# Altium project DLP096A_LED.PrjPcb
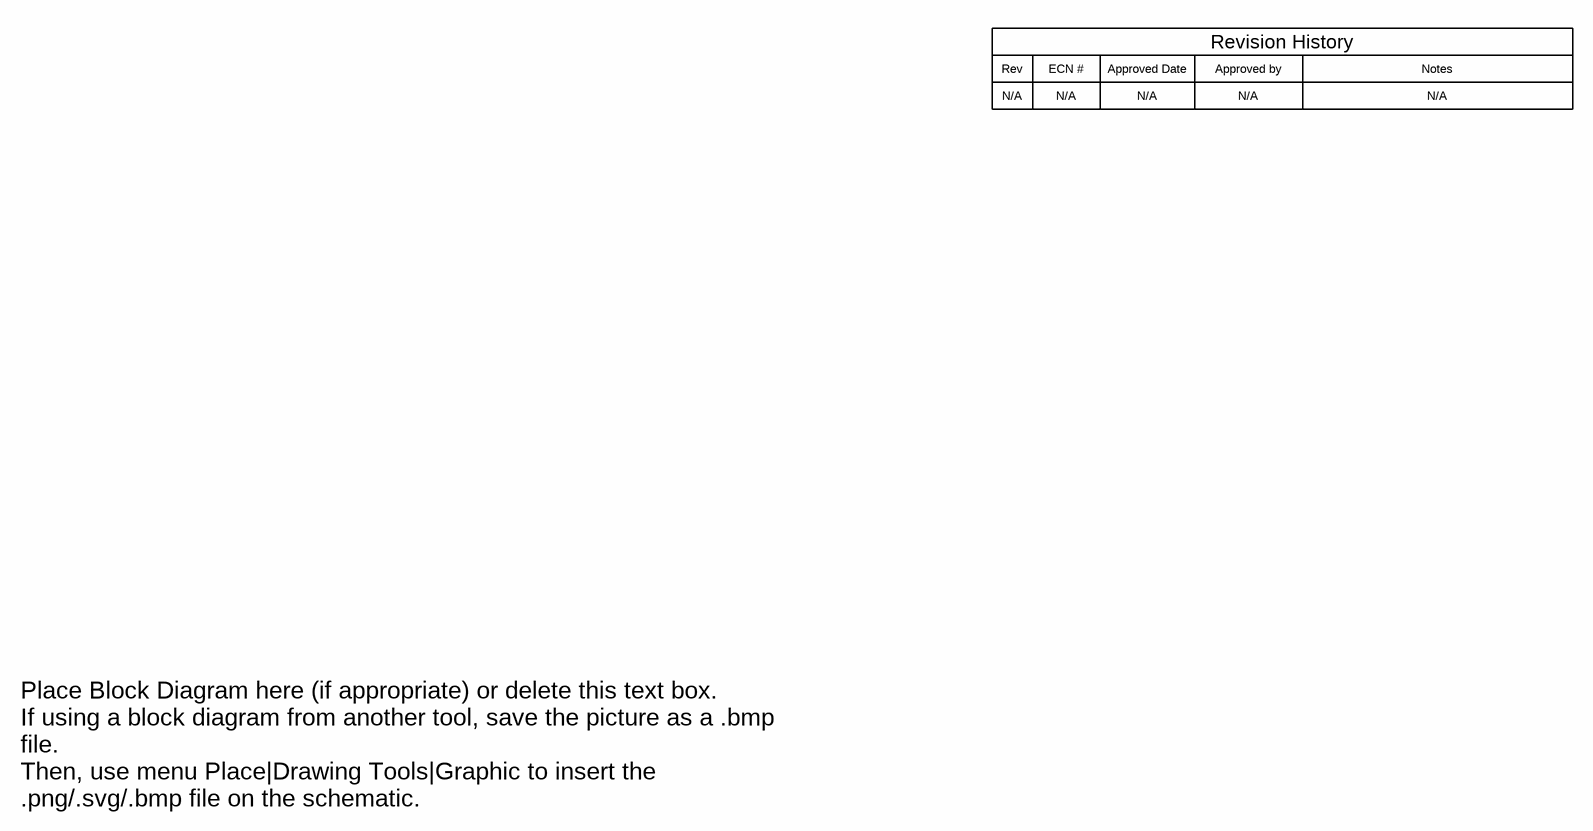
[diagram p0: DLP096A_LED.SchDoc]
CopyrightYear: 2023; PCB_Layout: A. Whitehead; PCB_Rev: A; PRJ_Customer: Public Release; PRJ_Engineer: A. Whitehead; PRJ_Number: DLP096A_LED; PRJ_Title: DLP2021AM263Q1EVM LED Adapter; SCH_Rev: A; TechSupport: http://www.ti.com/support; TID: N/A
3 sheets, 11 parts. Net scope: global (net labels, ports and power ports of the same name join across sheets).
Board file: DLP096A_LED.PcbDoc
Sheets:
  DLP096A_LED.SchDoc
  DLP096A_LED_BlankSheet.SchDoc
  DLP096A_LED_Hardware.SchDoc

## Sheet DLP096A_LED.SchDoc
size 431 x 279 mm; Date: Not shown in title block; ApprovedBy: Not shown in title block; CheckedBy: Not shown in title block; Author: Not shown in title block; CompanyName: Not shown in title block; Engineer: Not shown in title block; Organization: Not shown in title block; Address1: Not shown in title block; Address2: Not shown in title block; Address3: Not shown in title block; Address4: Not shown in title block; DocumentNumber: 1; Revision: Use project parameter SCH_Rev; SheetNumber: 1; SheetTotal: 3; PageSetup: Record=PageOptions¦CenterHorizontal=True¦CenterVertical=True¦PrintScale=1.00¦XCorrection=1.00¦YCorrection=1.00¦PrintKind=0¦BorderSize=5000000¦LeftOffset=0¦BottomOffset=0¦Orientation=2¦PaperLength=1000¦PaperWidth=1000¦Scale=100¦PaperSource=15¦PrintQuality=600¦MediaType=1¦DitherType=10¦PaperKind=Letter¦PrintScaleMode=1

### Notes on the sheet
- Rev
- N/A
- ECN #
- Approved Date
- Approved by
- Revision History
- Notes
- Place Block Diagram here (if appropriate) or delete this text box.
  If using a block diagram from another tool, save the picture as a .bmp file.
  Then, use menu Place|Drawing Tools|Graphic to insert the .png/.svg/.bmp file on the schematic.

## Sheet DLP096A_LED_BlankSheet.SchDoc
size 431 x 279 mm; Date: Not shown in title block; ApprovedBy: Not shown in title block; CheckedBy: Not shown in title block; Author: Not shown in title block; CompanyName: Not shown in title block; Engineer: Not shown in title block; Organization: Not shown in title block; Address1: Not shown in title block; Address2: Not shown in title block; Address3: Not shown in title block; Address4: Not shown in title block; DocumentNumber: 2; Revision: Use project parameter SCH_Rev; SheetNumber: 2; SheetTotal: 3; PageSetup: Record=PageOptions¦CenterHorizontal=True¦CenterVertical=True¦PrintScale=1.00¦XCorrection=1.00¦YCorrection=1.00¦PrintKind=0¦BorderSize=5000000¦LeftOffset=0¦BottomOffset=0¦Orientation=2¦PaperLength=1000¦PaperWidth=1000¦Scale=100¦PaperSource=15¦PrintQuality=600¦MediaType=1¦DitherType=10¦PaperKind=Letter¦PrintScaleMode=1
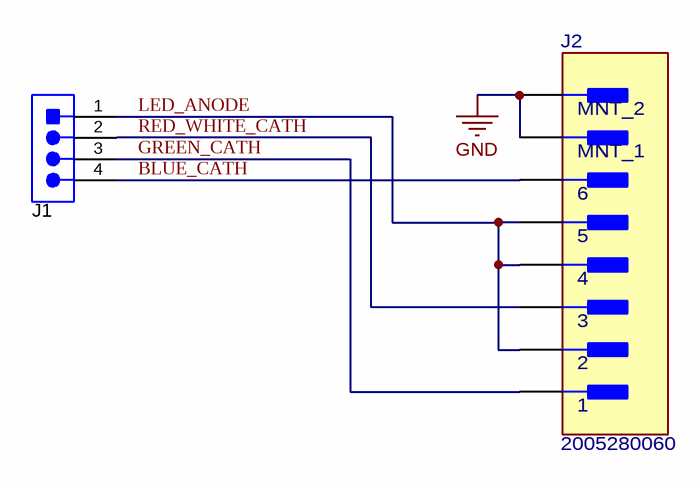
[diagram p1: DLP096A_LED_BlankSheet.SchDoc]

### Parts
J1  TSW-104-07-G-S  [TSW-104-07-G-S]  (value not drawn)
J2  2005280060  [FP-2005280060_CONN_11MM2_5MM25-MFG]

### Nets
GND: J2.7(MNT_1) J2.8(MNT_2)
BLUE_CATH: J1.4 J2.6
GREEN_CATH: J1.3 J2.1
LED_ANODE: J1.1 J2.2 J2.4 J2.5
RED_WHITE_CATH: J1.2 J2.3

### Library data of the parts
J1 = CMP-0075409-2: Header, 100mil, 4x1, Gold, TH; Manufacturer: Samtec; Pitch_mm: 2.54; Cert_VDE: N; Gender: Male; Cert_CSA: Y; Voltage_V: 550V; Green_REACh: Passed; Current_A: 6.3A; Green_Lifecycle: Active; Row_Count: 1
J2 = CMP-0090189-1: 6 Position FFC, FPC Connector Contacts, Bottom 0.039" (1.00mm) Surface Mount, Right Angle from Molex; Conn Gender: Male; Is Female: yes; DUT-Pitch_mm: 1mm; ContactFinish: Gold,Nickel; SizeZ_mm: 4.15mm; Voltage_V: 125V; AEC Qualified: No; Current_A: 1A

## Sheet DLP096A_LED_Hardware.SchDoc
size 431 x 279 mm; Date: Not shown in title block; ApprovedBy: Not shown in title block; CheckedBy: Not shown in title block; Author: Not shown in title block; CompanyName: Not shown in title block; Engineer: Not shown in title block; Organization: Not shown in title block; Address1: Not shown in title block; Address2: Not shown in title block; Address3: Not shown in title block; Address4: Not shown in title block; DocumentNumber: 3; Revision: Use project parameter SCH_Rev; SheetNumber: 3; SheetTotal: 3; PageSetup: Record=PageOptions¦CenterHorizontal=True¦CenterVertical=True¦PrintScale=1.00¦XCorrection=1.00¦YCorrection=1.00¦PrintKind=0¦BorderSize=5000000¦LeftOffset=0¦BottomOffset=0¦Orientation=2¦PaperLength=1000¦PaperWidth=1000¦Scale=100¦PaperSource=15¦PrintQuality=600¦MediaType=1¦DitherType=10¦PaperKind=Letter¦PrintScaleMode=1
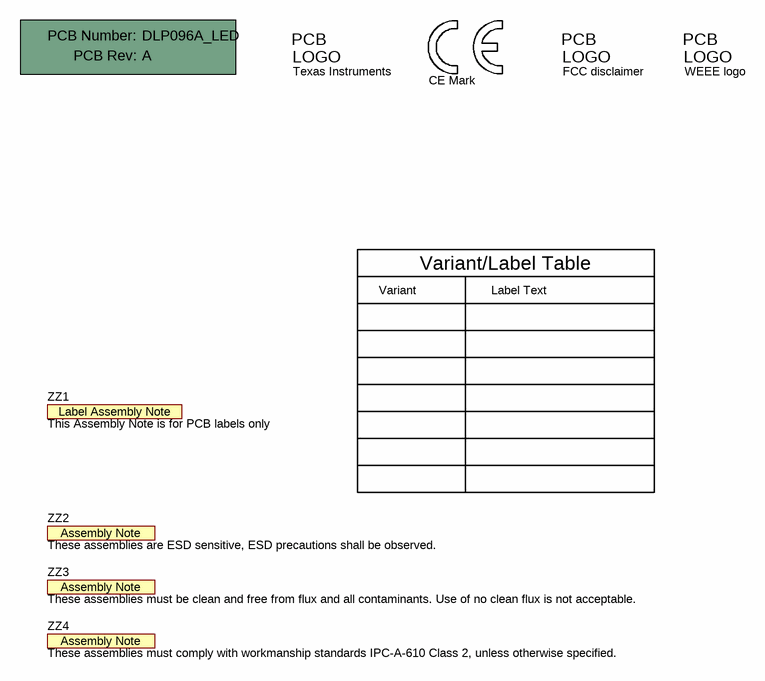
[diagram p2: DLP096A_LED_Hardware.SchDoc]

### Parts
!PCB  Printed Circuit Board  (value not drawn)  (mechanical)
Logo1  Texas Instruments  [TI_Symbol_Overlay_Small]  (no BOM)
Logo2  CE Mark  [CE_Mark_5mm]  (no BOM)
Logo3  FCC disclaimer  [FCC_disclaimer]  (no BOM)
Logo4  WEEE logo  [WEEE_Minimum]  (no BOM)
ZZ1  This Assembly Note is for PCB labels only  [AssemblyNoteLabel]  (no BOM)
ZZ2  These assemblies are ESD sensitive, ESD precautions shall be observed.  [AssemblyNote]  (no BOM)
ZZ3  These assemblies must be clean and free from flux and all contaminants. Use of no clean flux is not acceptable.  [AssemblyNote]  (no BOM)
ZZ4  These assemblies must comply with workmanship standards IPC-A-610 Class 2, unless otherwise specified.  [AssemblyNote]  (no BOM)

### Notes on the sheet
- Variant
- Variant/Label Table
- Label Text

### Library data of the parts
!PCB = CMP-0003618-2: Manufacturer: Any; PartNumber: DLP096A_LED
Logo1 = CMP-0074838-1: Texas Instrument Corporate Signature; SymbolCreator: a0412235; Lib Reference: TI_Logo; Library Reference: Logo
Logo2 = CMP-0074844-1: SymbolCreator: a0412235
Logo3 = CMP-0074847-1: FCC_disclaimer; Library Reference: Logo
Logo4 = CMP-0074769-1
ZZ1 = CMP-0003616-3
ZZ2 = CMP-0077236-1
ZZ3 = CMP-0077237-1
ZZ4 = CMP-0077238-1

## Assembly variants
001: not fitted FID1 FID2 FID3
